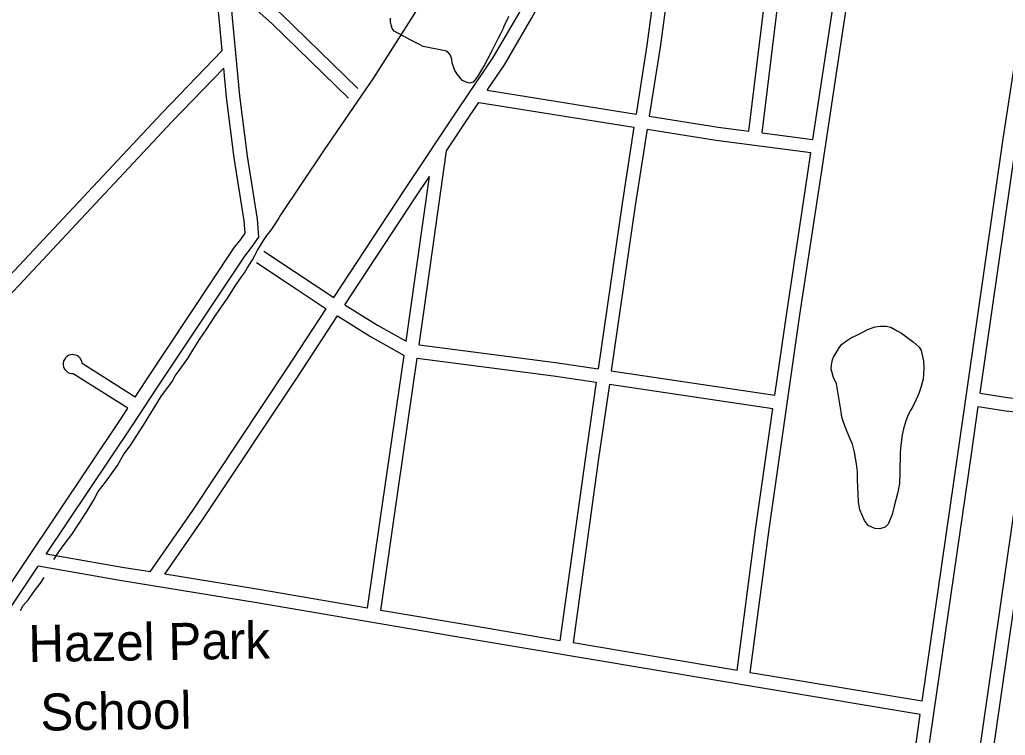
# Model space of a CAD drawing. Extents: x 3625074 to 3663148, y 511451 to 537151.
# Drawn here: x 3636148 to 3638362, y 526169 to 527777 of the extents above; entities that cross this region are included whole.
import ezdxf

# ---------------------------------------------------------------- set-up
doc = ezdxf.new("R2010")
doc.units = 0
for name, color, linetype in [('V-BLDG-IDEN', 7, 'Continuous'), ('V-ROAD-CNTR', 7, 'Continuous'), ('V-SITE-VEGE', 7, 'Continuous'), ('V-TOPO-SHOR', 7, 'Continuous')]:
    doc.layers.add(name, color=color, linetype=linetype)

msp = doc.modelspace()

# ---------------------------------------------------------------- linework, layer by layer
at = {"layer": 'V-ROAD-CNTR'}
for p, q in [((3636407.2, 526928.5), (3636288.2, 527003.9)), ((3636390.7, 526903.5), (3636268.2, 526981.1))]:
    msp.add_line(p, q, dxfattribs=at)
for points in [[(3636602.6, 527707.5), (3636573.4, 528019.5), (3636532.1, 528412.9), (3636483.5, 528889.4)], [(3636853.2, 527152.2), (3637011.3, 527392.8), (3637133.7, 527576.5), (3637211.3, 527691.4), (3637272.1, 527795.1), (3637295.9, 527839.6), (3637299.3, 527869.1), (3637318.7, 528001.5), (3637354.4, 528189.2), (3637379, 528271.2), (3637417.8, 528323.2)], [(3637197.9, 527618), (3637236.7, 527675.4), (3637298.3, 527780.4), (3637325, 527830.5), (3637329, 527865.2), (3637348.3, 527996.6), (3637383.5, 528182.1), (3637406.2, 528257.5), (3637430.6, 528290.2)], [(3637629.6, 528253.4), (3637611.4, 528124), (3637556.7, 527719.1), (3637532.6, 527564.6)], [(3637659.1, 528248.2), (3637641.1, 528119.9), (3637586.4, 527714.7), (3637562.2, 527559.9)], [(3637786.1, 527526.3), (3637821.3, 527814.7), (3637877.4, 528216)], [(3637815.8, 527522.4), (3637851.1, 527810.9), (3637907.1, 528211.9)], [(3637789, 526309.2), (3637830.5, 526626), (3637900.7, 527113.4), (3637948.8, 527432.6), (3638063.3, 528188.8)], [(3637929.8, 527507.7), (3638033.7, 528193.4)], [(3638175.5, 526245.3), (3638256.4, 526804.8), (3638357.4, 527509), (3638427.4, 527967.7), (3638449.7, 528125.8)], [(3636615, 527897.3), (3636735.8, 527789), (3636907.7, 527622.1)], [(3636207.5, 526575.7), (3636400.7, 526864.1), (3636456.1, 526948.3), (3636653.4, 527245.4), (3636668.4, 527264.5), (3636685, 527288), (3636681.9, 527328), (3636659.3, 527470.1), (3636642.3, 527605.5), (3636619.1, 527853.3)], [(3636619.1, 527853.3), (3636715.3, 527767.1), (3636886.8, 527600.5)], [(3635589.5, 526826.5), (3635687.8, 526909.6), (3635793.5, 527021.3), (3635824.2, 527047.2), (3635853.6, 527048.5), (3635869.2, 527049.1), (3635886.6, 527041.7), (3635907.5, 527020), (3635916.1, 527012.5), (3635924.9, 527008.8), (3635934.7, 527009.8), (3635951.5, 527019.4), (3635999.6, 527069.9), (3636123.8, 527200.2), (3636468.2, 527567.4), (3636602.6, 527707.5)], [(3635608.9, 526803.6), (3635708.5, 526887.8), (3635814.1, 526999.4), (3635835.7, 527017.7), (3635854.8, 527018.6), (3635863.6, 527018.9), (3635869.2, 527016.5), (3635886.8, 526998.2), (3635900, 526986.7), (3635920.4, 526978.1), (3635944.2, 526980.6), (3635970.2, 526995.6), (3636021.3, 527049.2), (3636145.6, 527179.5), (3636489.9, 527546.7), (3636606.3, 527668)], [(3636407.2, 526928.5), (3636431.1, 526964.9), (3636629.1, 527263), (3636644.4, 527282.5), (3636654.3, 527296.5), (3636652.1, 527324.5), (3636629.6, 527465.9), (3636612.5, 527602.3), (3636606.3, 527668)], [(3637197.9, 527618), (3637532.6, 527564.6)], [(3637106.7, 527482), (3637158.6, 527559.8), (3637179.4, 527590.6)], [(3637179.4, 527590.6), (3637527.9, 527535)], [(3638305.7, 526937.2), (3638387, 527504.6), (3638397.2, 527571.4)], [(3637562.2, 527559.9), (3637717, 527535.2), (3637786.1, 527526.3)], [(3637527.9, 527535), (3637501.1, 527363.4), (3637447.2, 526991.9)], [(3637557.6, 527530.2), (3637530.8, 527358.9), (3637476.9, 526987.5)], [(3637557.6, 527530.2), (3637712.7, 527505.5), (3637925.3, 527478.1)], [(3637815.8, 527522.4), (3637929.8, 527507.7)], [(3637044.9, 527045.8), (3637055.4, 527119.1), (3637106.7, 527482)], [(3637844.4, 526932.8), (3637871, 527117.8), (3637919.1, 527437.1), (3637925.3, 527478.1)], [(3636878.4, 527135.9), (3637036.3, 527376.3), (3637068.3, 527424.3)], [(3637015.7, 527053.9), (3637025.7, 527123.4), (3637068.3, 527424.3)], [(3636696.4, 527256.2), (3636765, 527210.4), (3636853.2, 527152.2)], [(3636679.7, 527231.2), (3636748.4, 527185.4), (3636836.7, 527127.1)], [(3636441.1, 526535.7), (3636536.7, 526673.8), (3636748.1, 526992.2), (3636836.7, 527127.1)], [(3636878.4, 527135.9), (3636951.4, 527090.1), (3637015.7, 527053.9)], [(3636473.8, 526530.3), (3636561.5, 526657), (3636773.1, 526975.7), (3636861.9, 527110.8)], [(3636861.9, 527110.8), (3636936.1, 527064.3), (3637011.2, 527022.1)], [(3637044.9, 527045.8), (3637351.6, 527006.2), (3637447.2, 526991.9)], [(3636929.3, 526454.3), (3636957.9, 526651.6), (3637011.2, 527022.1)], [(3636958.9, 526449.2), (3636987.5, 526647.3), (3637040.6, 527016.1)], [(3637040.6, 527016.1), (3637347.4, 526976.5), (3637442.9, 526962.2)], [(3637476.9, 526987.5), (3637753.8, 526946.1), (3637844.4, 526932.8)], [(3637442.9, 526962.2), (3637418.6, 526794.5), (3637361.3, 526381.1)], [(3637472.6, 526957.8), (3637448.3, 526790.3), (3637390.9, 526376.2)], [(3637472.6, 526957.8), (3637749.4, 526916.5), (3637840.1, 526903.1)], [(3638305.7, 526937.2), (3638366.9, 526927.5), (3638418.9, 526921.8)], [(3635702.9, 525898.3), (3635733.4, 525926), (3635757.6, 525952.6), (3636014.6, 526341.6), (3636375.7, 526880.7), (3636390.7, 526903.5)], [(3637759.4, 526314.2), (3637800.8, 526630.1), (3637840.1, 526903.1)], [(3638072, 525340.3), (3638099.2, 525526.2), (3638188.4, 526124.5), (3638286, 526800.5), (3638301.4, 526907.5)], [(3638301.4, 526907.5), (3638362.9, 526897.8), (3638414.5, 526892.1)], [(3638190.9, 525325.9), (3638208.3, 525460.3), (3638252.3, 525779.5), (3638311, 526177.7), (3638391.1, 526734.1), (3638414.5, 526892.1)], [(3638255, 525579.7), (3638282, 525775.2), (3638340.7, 526173.4), (3638420.7, 526729.7), (3638444.4, 526888.9)], [(3636441.1, 526535.7), (3636378, 526545.9), (3636207.5, 526575.7)], [(3635707, 525861.5), (3635754.7, 525904.7), (3635781.4, 525934.2), (3636039.5, 526324.9), (3636189.2, 526548.4)], [(3638171.2, 526215.6), (3637830.1, 526271.9), (3637164.4, 526383.8), (3636680.3, 526466.2), (3636373, 526516.4), (3636189.2, 526548.4)], [(3636929.3, 526454.3), (3636685.3, 526495.8), (3636473.8, 526530.3)], [(3637361.3, 526381.1), (3637169.4, 526413.4), (3636958.9, 526449.2)], [(3637759.4, 526314.2), (3637390.9, 526376.2)], [(3638175.5, 526245.3), (3637835, 526301.5), (3637789, 526309.2)], [(3638090.2, 525669.2), (3638158.7, 526128.8), (3638171.2, 526215.6)]]:
    msp.add_lwpolyline(points, dxfattribs=at)
msp.add_arc((3636266.8, 527002.5), 21.4, 3.851, 273.6997, dxfattribs=at)
at = {"layer": 'V-SITE-VEGE'}
msp.add_lwpolyline([(3637245.7, 527783.4), (3637242.1, 527774.4), (3637235.7, 527762.1), (3637234, 527757), (3637228.1, 527744.6), (3637222.9, 527735.1), (3637214.7, 527718.8), (3637208.9, 527706.4), (3637198.5, 527687.9), (3637192, 527675), (3637182.8, 527660.4), (3637178.1, 527650.9), (3637171.2, 527641.3), (3637166.6, 527636.3), (3637158.6, 527634.2), (3637150.7, 527636.5), (3637142.3, 527640), (3637137.3, 527645.8), (3637130.6, 527653.8), (3637124.5, 527664.1), (3637119.7, 527679.4), (3637118.7, 527687.4), (3637115.4, 527696.5), (3637111.5, 527702.2), (3637109.3, 527703.9), (3637107.6, 527706.2), (3637054, 527716.6), (3637046.1, 527720.7), (3637025.3, 527731.1), (3637011.9, 527738.7), (3636996.1, 527746.8), (3636988.8, 527750.9), (3636984.4, 527756.6), (3636982.8, 527761.7), (3636981.2, 527772), (3636980.8, 527779.9)], dxfattribs=at)
msp.add_lwpolyline([(3637983.1, 526958.5), (3637976.5, 526972.2), (3637971.1, 526991.5), (3637971.3, 527001.1), (3637973.7, 527012.4), (3637976, 527018), (3637982.4, 527028.1), (3637987.6, 527037.1), (3637994, 527046.6), (3638005.4, 527055), (3638016.9, 527062.7), (3638027.1, 527067.1), (3638040.2, 527073.7), (3638052.2, 527080.3), (3638069.8, 527086.3), (3638081.2, 527087.8), (3638094.7, 527087.6), (3638104.9, 527085.8), (3638119.5, 527077.6), (3638129, 527071.9), (3638144.2, 527060.9), (3638154.8, 527052.8), (3638168.8, 527040.7), (3638173.2, 527033.3), (3638176.4, 527019.7), (3638178, 527010), (3638178.8, 526992.5), (3638178.7, 526980.6), (3638177.9, 526968.7), (3638172.6, 526950.1), (3638167.8, 526936.6), (3638162, 526923.1), (3638153.8, 526906.2), (3638148.6, 526897.3), (3638142.2, 526884.9), (3638138.7, 526875.3), (3638133.3, 526857.3), (3638130.3, 526843.8), (3638127.1, 526820.6), (3638125.8, 526804.2), (3638125.1, 526757.8), (3638124.2, 526734.6), (3638120.5, 526714.9), (3638112.7, 526683.3), (3638107.9, 526664.7), (3638098.6, 526643.3), (3638092.2, 526636.1), (3638080.3, 526632.3), (3638069, 526633), (3638053.8, 526640), (3638045.5, 526651.4), (3638035.1, 526674.8), (3638032.5, 526693.5), (3638030.4, 526743.3), (3638030.1, 526760.9), (3638028.1, 526778.5), (3638023.3, 526805.1), (3638019.1, 526822.7), (3638013, 526836.4), (3638007, 526850.6), (3637999.4, 526870), (3637996.1, 526879.1), (3637994, 526887), (3637994, 526891)], close=True, dxfattribs=at)
at = {"layer": 'V-TOPO-SHOR'}
for points in [[(3636732.2, 527334.2), (3636832.9, 527484.4), (3636943.2, 527646), (3637037.5, 527793.9), (3637143, 527951), (3637234.2, 528091.3), (3637312.4, 528212.7), (3637416.2, 528372.1), (3637519.9, 528525.7), (3637611.7, 528664.9), (3637741.7, 528864.1), (3637844.2, 529014.2), (3637918.9, 529133.8), (3637968.3, 529205.4), (3638049.4, 529331.9), (3638121.6, 529438.8), (3638188.9, 529535.7), (3638230.7, 529606.3), (3638267.1, 529665.2), (3638337.3, 529761.6), (3638406.7, 529881.8)], [(3636224.2, 526563.2), (3636236.1, 526580.8), (3636247.4, 526597), (3636265.3, 526619.4), (3636279.2, 526641.2), (3636298.4, 526671.5), (3636314.5, 526697.9), (3636324, 526716.7), (3636340.3, 526737.1), (3636367.6, 526775.1), (3636381.4, 526800), (3636395.8, 526818.8), (3636411, 526842.2), (3636425.6, 526865.7), (3636442.4, 526892.4), (3636455.9, 526914.4), (3636466.6, 526931.2), (3636482.7, 526953.4), (3636490, 526963.9), (3636497.3, 526976.2), (3636503.5, 526985.5), (3636525.6, 527015.4), (3636536.5, 527033.9), (3636551.7, 527058.1), (3636568.4, 527081.6), (3636584.9, 527107.2), (3636599, 527128.2), (3636615.1, 527151.4), (3636632.8, 527178.9), (3636645.9, 527198.6), (3636652.6, 527208.1), (3636658.8, 527218), (3636665.7, 527228.5), (3636670.7, 527236.8), (3636676.4, 527246.7), (3636682.4, 527258.4), (3636688.7, 527269.3), (3636695.8, 527280.4), (3636703.4, 527291.3), (3636712.7, 527303.8), (3636723.1, 527319.5), (3636728.2, 527327.6), (3636732.2, 527334.2)], [(3636149.5, 526449.1), (3636155.8, 526460.1), (3636167.6, 526473.9), (3636175.5, 526486), (3636185.5, 526499.1), (3636194.8, 526510.6), (3636202.6, 526523.1)]]:
    msp.add_lwpolyline(points, dxfattribs=at)

# ---------------------------------------------------------------- texts
at = {"layer": 'V-BLDG-IDEN'}
for s, p in [('Hazel Park', (3636167.8, 526333.1)), ('School', (3636194.8, 526178.8))]:
    msp.add_text(s, height=83, rotation=0.8488, dxfattribs=at).set_placement(p)

doc.saveas('drawing.dxf')
